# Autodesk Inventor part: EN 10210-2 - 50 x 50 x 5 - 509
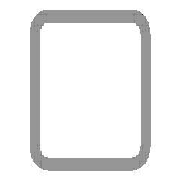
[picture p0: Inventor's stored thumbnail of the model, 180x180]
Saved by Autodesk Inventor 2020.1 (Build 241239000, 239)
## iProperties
Created: 2019-10
Part Number: EN 10210-2 - 50 x 50 x 5 - 509
Material: Stahl, weich
Description: Rohrleitung
Document SubType Name: Modeling
Standard: DIN
Designer: lutzd
Standard Revision: 2006-07
Standards Organization: DIN
Language: de-DE
Size Designation: 50 x 50 x 5
Categories: <MemberInstance><Categories><Category DisplayName="Profile" InternalName="089c4875-fa83-4c05-b084-43b9cc11f5ed" Mnemonic="GRDR"><CategoryParameter DisplayName="
Stock Number: 50 x 50 x 5
Mass: 3488.9 g
Surface Area: 1740.63 cm^2
Volume: 444.446 cm^3
Density: 7.85 g/cm^3
Appearance: Halbpoliert
IsCustomPart: 1
G_W: 50,000 mm
G_H: 50,000 mm
Dimensions: 50x50x509 mm
Mass: 3,489 kg
DocNumber: ADSK-014219
Folder: .
+A4F13F7C-EF39-42E3-8869-708D840C18BC+SCHNITTDETAIL1: Schnittwinkel 90,00 grd
G_L: 509,000 mm
_CCFamilyMember: 16
_CCFamilyDisplayName: DIN EN 10210-2 (USAS B17.1 quadratisch) - Rohrleitung — In Klammern angegebene Größen wurden aufgehoben
_FrameMemberDoc: Frame Member File
_Version: 15.0.0
_GetPNFromCC: 1
Title: Profil-Bauteil
Author: lutzd
Revision Number: -
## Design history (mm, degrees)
node "Startebene"
node "Endebene"
sketch "Skizze"
  geometry: L1 (-25, -17.5)-(-25, 17.5); L2 (-17.5, 25)-(17.5, 25); L3 (25, 17.5)-(25, -17.5); L4 (17.5, -25)-(-17.5, -25); L5 (-15, 20)-(15, 20); L6 (20, 15)-(20, -15); L7 (15, -20)-(-15, -20); L8 (-20, -15)-(-20, 15); L9 (0, 37.175)-(0, -37.175) reference; L10 (-37.175, 0)-(37.175, 0) reference; A1 r 7.5 centre (-17.5, -17.5) between (-25, -17.5) and (-17.5, -25); A2 r 7.5 centre (-17.5, 17.5) between (-17.5, 25) and (-25, 17.5); A3 r 7.5 centre (17.5, 17.5) between (25, 17.5) and (17.5, 25); A4 r 7.5 centre (17.5, -17.5) between (17.5, -25) and (25, -17.5); A5 r 5 centre (-15, -15) between (-20, -15) and (-15, -20); A6 r 5 centre (-15, 15) between (-15, 20) and (-20, 15); A7 r 5 centre (15, 15) between (20, 15) and (15, 20); A8 r 5 centre (15, -15) between (15, -20) and (20, -15)
  constraints: 16 end point, 16 point on circle, 16 tangent, 8 centre point, 6 equal radius, 4 parallel, 2 perpendicular, 2 other
  dimensions: "d7" = 7.5 radius of A1 (= G_IR); "d10" = 50 distance between parallel lines of L2 L4 (= G_H); "d11" = 50 distance between parallel lines of L1 L3 (= G_W); "d12" = 5 distance between parallel lines of L3 L6 (= G_T); "d15" = 25 distance between parallel lines of L2 L10 (= 0.5 x d10); "d16" = 25 distance between parallel lines of L9 L3 (= 0.5 x d11); "d19" = 5 radius of A5 (= G_T); "d20" = 5 distance between parallel lines of L4 L7 (= G_T)
extrude "Körper" new body sketch "Skizze" stored distance "d3" = 509 (= G_L); taper "d4" = 0 deg
node "Driven Length"
  sketch "Sketch3"
    geometry: L1 (0, 0)-(10, 0) reference
    constraints: 2 end point, 1 horizontal
  workplane "Work Plane3"
  sketch "Sketch4"
    geometry: L1 (-2, 0)-(12, 0) reference; L2 (-2, 509)-(12, 509) reference
    dimensions: "d18" = 509 distance between parallel lines of L1 L2 (derived)
workplane "Arbeitsebene4"
feature "Trennen1"
body "Solid1"
other parameters: "G_W" = 50 [user parameter; used in 1 equation term], "G_H" = 50 [user parameter; used in 1 equation term], "G_T" = 5 [user parameter; used in 3 equation terms], "G_IR" = 7.5 [user parameter; used in 1 equation term], "G_L" = 509 (= d18) [user parameter; used in 1 equation term], "G_OFFSET_START" = 0 [user parameter; used in 1 equation term], "d13" = 0 (computed from G_OFFSET_START), "d14" = 509 (= G_OFFSET_END + B_L), "B_L" = 559 [user parameter; used in 1 equation term], "d17" = 90 deg
